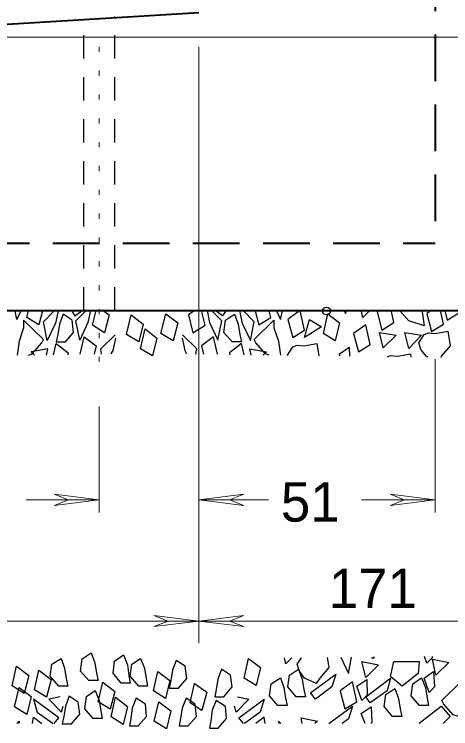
# Model space of a CAD drawing. Extents: x 312583 to 312854, y 144419 to 144597.
# Drawn here: x 312715.73 to 312724.13, y 144443.55 to 144457.33 of the extents above; entities that cross this region are included whole.
import ezdxf

# ---------------------------------------------------------------- set-up
doc = ezdxf.new("R2010")
doc.units = 0
doc.header["$LTSCALE"] = 0.3
doc.header["$PDMODE"] = 32
doc.header["$PDSIZE"] = 0.15
for name, pattern in [('DOTTED', [1.5, 0.3, -1.2]), ('MEDIUM_DASHED', [4.5, 3, -1.5]), ('SHORT_DASHED', [2.7, 1.5, -1.2])]:
    doc.linetypes.add(name, pattern=pattern)
doc.layers.add('1', color=7, linetype='Continuous', lineweight=25)
doc.layers.add('2', color=7, linetype='Continuous', lineweight=13)

msp = doc.modelspace()

# ---------------------------------------------------------------- linework, layer by layer
at = {"layer": '1', "linetype": 'MEDIUM_DASHED', "lineweight": 40}
for p in [(312723.8344, 144494.7404), (312698.9177, 144452.9187)]:
    msp.add_line(p, (312723.8344, 144452.9187), dxfattribs=at)
at = {"layer": '1', "lineweight": 40}
for p, q in [((312711.376, 144456.89), (312719.2804, 144457.3654)), ((312697.001, 144451.6154), (312725.751, 144451.6154))]:
    msp.add_line(p, q, dxfattribs=at)
at = {"layer": '1', "linetype": 'SHORT_DASHED'}
for p, q in [((312717.0647, 144451.6154), (312717.0647, 144457.258)), ((312717.6627, 144451.6154), (312717.6627, 144457.2964))]:
    msp.add_line(p, q, dxfattribs=at)
at = {"layer": '1'}
for p, q in [((312715.9684, 144451.485), (312715.999, 144451.6077)), ((312716.2904, 144451.4007), (312716.4974, 144451.6077)), ((312716.9114, 144451.416), (312717.1107, 144451.6154)), ((312717.2334, 144451.3317), (312717.3024, 144451.6154)), ((312719.403, 144451.3317), (312719.334, 144451.6154)), ((312719.725, 144451.416), (312719.5257, 144451.6154)), ((312720.346, 144451.4007), (312720.139, 144451.6077)), ((312720.668, 144451.485), (312720.6374, 144451.6077)), ((312721.3197, 144451.2397), (312721.2354, 144451.6077)), ((312723.037, 144451.3854), (312722.991, 144451.6)), ((312723.9954, 144451.3547), (312723.9417, 144451.5924)), ((312717.3944, 144450.8794), (312717.6704, 144451.1477)), ((312719.242, 144450.8794), (312718.966, 144451.1477)), ((312717.4097, 144450.772), (312717.3944, 144450.8794)), ((312719.2267, 144450.772), (312719.242, 144450.8794)), ((312722.1784, 144450.91), (312722.186, 144450.7337)), ((312716.0527, 144450.818), (312716.114, 144450.7567)), ((312720.5837, 144450.818), (312720.5224, 144450.7567)), ((312723.9494, 144450.7337), (312723.9417, 144450.7107)), ((312716.6124, 144444.1634), (312716.39, 144444.1174)), ((312720.024, 144444.1634), (312720.2464, 144444.1174)), ((312716.1677, 144443.872), (312716.4744, 144443.6497)), ((312720.461, 144443.872), (312720.162, 144443.6497)), ((312721.565, 144443.6957), (312721.519, 144443.6497)), ((312722.163, 144443.7417), (312722.0404, 144443.6497))]:
    msp.add_line(p, q, dxfattribs=at)
for points in [[(312715.8534, 144451.6077), (312715.7767, 144451.4467), (312715.746, 144451.6077)], [(312716.2674, 144451.6077), (312716.1984, 144451.3394), (312715.9684, 144451.485)], [(312716.574, 144451.6077), (312716.5204, 144451.37), (312716.3594, 144451.0404), (312716.2904, 144451.4007)], [(312716.827, 144451.6154), (312716.896, 144451.5157), (312717.0034, 144451.5924), (312717.0264, 144451.6154)], [(312717.195, 144451.6154), (312717.1414, 144451.3854), (312716.988, 144451.048), (312716.9114, 144451.416)], [(312717.4404, 144451.6154), (312717.5554, 144451.531), (312717.4634, 144451.186), (312717.2334, 144451.3317)], [(312719.196, 144451.6154), (312719.081, 144451.531), (312719.1654, 144451.186), (312719.403, 144451.3317)], [(312719.4414, 144451.6154), (312719.4874, 144451.3854), (312719.6484, 144451.048), (312719.725, 144451.416)], [(312719.8094, 144451.6154), (312719.7404, 144451.5157), (312719.633, 144451.5924), (312719.6024, 144451.6154)], [(312720.0624, 144451.6077), (312720.116, 144451.37), (312720.277, 144451.0404), (312720.346, 144451.4007)], [(312720.369, 144451.6077), (312720.438, 144451.3394), (312720.668, 144451.485)], [(312720.7754, 144451.6077), (312720.852, 144451.4467), (312720.8904, 144451.6077)], [(312721.22, 144451.6077), (312720.9977, 144451.4467), (312721.0897, 144451.094), (312721.3197, 144451.2397)], [(312722.0864, 144451.6), (312722.1094, 144451.5617), (312722.117, 144451.6)], [(312722.554, 144451.6), (312722.439, 144451.485), (312722.416, 144451.6)], [(312722.7304, 144451.6), (312722.715, 144451.5924), (312722.807, 144451.2397), (312723.037, 144451.3854)], [(312723.5814, 144451.5924), (312723.6197, 144451.324), (312723.3284, 144451.416), (312723.1674, 144451.6)], [(312723.727, 144451.5924), (312723.6734, 144451.5617), (312723.7654, 144451.209), (312723.9954, 144451.3547)], [(312724.026, 144451.5924), (312724.0644, 144451.4314), (312724.302, 144451.577)], [(312715.999, 144450.7567), (312716.068, 144450.7797), (312716.2597, 144450.9944), (312716.2904, 144451.0557), (312715.907, 144451.4314), (312715.907, 144451.2857)], [(312720.6374, 144450.7567), (312720.5684, 144450.7797), (312720.3767, 144450.9944), (312720.346, 144451.0557), (312720.7294, 144451.4314), (312720.7294, 144451.2857)], [(312715.907, 144451.2857), (312715.8227, 144451.025), (312715.7844, 144450.7567)], [(312720.7294, 144451.2857), (312720.8137, 144451.025), (312720.852, 144450.7567)], [(312723.6964, 144450.7184), (312723.658, 144450.7337), (312723.5584, 144450.864), (312723.52, 144450.9944), (312723.6197, 144451.1554), (312723.704, 144451.186), (312723.8344, 144451.1707), (312724.0797, 144451.2167), (312724.1257, 144450.933), (312723.9494, 144450.7337)], [(312716.9957, 144450.772), (312717.0724, 144451.1094), (312717.3024, 144450.933), (312717.264, 144450.772)], [(312717.678, 144451.0864), (312717.6244, 144450.8487), (312717.586, 144450.7797)], [(312718.9584, 144451.0864), (312719.012, 144450.8487), (312719.0427, 144450.7797)], [(312719.6407, 144450.772), (312719.564, 144451.1094), (312719.334, 144450.933), (312719.3724, 144450.772)], [(312716.344, 144450.7567), (312716.3747, 144450.8794), (312716.0527, 144450.818)], [(312716.482, 144450.7644), (312716.5357, 144450.979), (312716.7657, 144450.8027), (312716.758, 144450.7644)], [(312720.1544, 144450.7644), (312720.1007, 144450.979), (312719.8707, 144450.8027), (312719.8784, 144450.7644)], [(312720.2924, 144450.7567), (312720.2617, 144450.8794), (312720.5837, 144450.818)], [(312720.99, 144450.749), (312720.99, 144450.7567), (312721.0897, 144450.9177), (312721.174, 144450.9484), (312721.3044, 144450.933), (312721.5574, 144450.979), (312721.5957, 144450.7414)], [(312722.002, 144450.7337), (312721.9867, 144450.772), (312722.1784, 144450.91)], [(312722.9144, 144450.726), (312722.9757, 144450.749), (312723.106, 144450.7337), (312723.359, 144450.7797), (312723.3667, 144450.7184)], [(312721.7567, 144444.9224), (312721.7874, 144444.7307), (312721.611, 144444.5237)], [(312722.0174, 144444.93), (312722.163, 144444.6157), (312722.2244, 144444.93)], [(312722.6614, 144444.9377), (312722.6307, 144444.907), (312722.6154, 144444.93)], [(312723.773, 144444.9454), (312723.7807, 144444.9224), (312723.6734, 144444.815), (312723.6274, 144444.9454)], [(312721.0744, 144444.9147), (312720.9594, 144444.7997), (312720.9287, 144444.9147)], [(312721.611, 144444.5237), (312721.542, 144444.424), (312721.3197, 144444.5237), (312721.22, 144444.6617), (312721.174, 144444.792), (312721.2584, 144444.9147)], [(312716.4974, 144443.6497), (312716.5817, 144443.757), (312716.0987, 144444.1174), (312716.1677, 144443.872)], [(312716.39, 144444.1174), (312716.6354, 144443.872), (312716.666, 144443.987)], [(312720.2464, 144444.1174), (312720.001, 144443.872), (312719.9704, 144443.987)], [(312720.139, 144443.6497), (312720.0547, 144443.757), (312720.5377, 144444.1174), (312720.461, 144443.872)], [(312721.7874, 144443.6497), (312722.2397, 144443.987), (312722.163, 144443.7417)], [(312722.485, 144443.6497), (312722.4084, 144443.8414), (312722.6, 144443.9717)], [(312722.6, 144443.9717), (312722.6154, 144443.6727), (312722.5924, 144443.6497)], [(312723.5354, 144443.6497), (312723.5277, 144443.6574), (312723.9494, 144443.987)], [(312723.9494, 144443.987), (312724.1257, 144443.7877), (312723.9877, 144443.6497)], [(312715.7767, 144443.6497), (312715.8227, 144443.6957), (312715.815, 144443.6497)], [(312716.0757, 144443.6497), (312716.0987, 144443.7724), (312716.2597, 144443.6497)], [(312720.5607, 144443.6497), (312720.5377, 144443.7724), (312720.3767, 144443.6497)], [(312720.8597, 144443.6497), (312720.8137, 144443.6957), (312720.8214, 144443.6497)], [(312721.2737, 144443.6497), (312721.2507, 144443.757), (312721.565, 144443.6957)]]:
    msp.add_lwpolyline(points, dxfattribs=at)
for points in [[(312716.666, 144451.5464), (312716.597, 144451.3547), (312716.5664, 144451.1554), (312716.5357, 144451.0097), (312716.712, 144451.0097), (312716.8654, 144451.1937), (312716.8424, 144451.4314)], [(312718.552, 144451.1707), (312718.644, 144451.554), (312718.874, 144451.3777), (312718.7897, 144451.0327)], [(312719.9704, 144451.5464), (312720.0394, 144451.3547), (312720.07, 144451.1554), (312720.1007, 144451.0097), (312719.9244, 144451.0097), (312719.7634, 144451.1937), (312719.794, 144451.4314)], [(312721.68, 144451.1707), (312721.7644, 144451.554), (312721.9944, 144451.3777), (312721.91, 144451.0327)], [(312717.885, 144451.1554), (312717.977, 144451.531), (312718.207, 144451.3547), (312718.1227, 144451.0097)], [(312721.6417, 144451.301), (312721.3197, 144451.094), (312721.4117, 144451.4467)], [(312718.161, 144450.8794), (312718.2454, 144451.2627), (312718.4754, 144451.0864), (312718.391, 144450.7414)], [(312722.5847, 144450.9637), (312722.5004, 144451.3394), (312722.2627, 144451.1707), (312722.3547, 144450.818)], [(312723.083, 144451.14), (312722.83, 144450.8947), (312722.761, 144451.1937)], [(312723.5737, 144451.14), (312723.3284, 144450.887), (312723.2517, 144451.1937)], [(312717.2104, 144445.0144), (312717.2794, 144444.8227), (312717.31, 144444.6234), (312717.3407, 144444.4777), (312717.1644, 144444.4777), (312717.0034, 144444.6617), (312717.034, 144444.8994)], [(312717.8314, 144444.976), (312717.908, 144444.7844), (312717.931, 144444.5774), (312717.9617, 144444.4317), (312717.7854, 144444.4317), (312717.632, 144444.6234), (312717.655, 144444.8534)], [(312716.6277, 144444.907), (312716.6967, 144444.7154), (312716.7274, 144444.516), (312716.758, 144444.3704), (312716.5817, 144444.3704), (312716.4207, 144444.562), (312716.4514, 144444.792)], [(312718.161, 144444.907), (312718.2377, 144444.7154), (312718.2684, 144444.516), (312718.2914, 144444.3704), (312718.1227, 144444.3704), (312717.9617, 144444.562), (312717.9924, 144444.792)], [(312718.8434, 144444.8687), (312718.7744, 144444.677), (312718.7437, 144444.4777), (312718.713, 144444.332), (312718.8894, 144444.332), (312719.0504, 144444.516), (312719.0197, 144444.7537)], [(312720.1544, 144444.5237), (312720.2387, 144444.907), (312720.4687, 144444.7307), (312720.3844, 144444.3857)], [(312722.7457, 144444.7844), (312722.5004, 144444.539), (312722.4237, 144444.8457)], [(312723.5047, 144444.6157), (312723.198, 144444.3704), (312722.9757, 144444.5544), (312723.037, 144444.8457), (312723.5277, 144444.8457)], [(312724.095, 144444.8304), (312723.8497, 144444.585), (312723.7807, 144444.8917)], [(312715.6847, 144444.378), (312715.769, 144444.7537), (312716.0067, 144444.5774), (312715.9147, 144444.2324)], [(312716.114, 144444.3014), (312716.1984, 144444.677), (312716.436, 144444.5007), (312716.344, 144444.1557)], [(312718.4064, 144444.2784), (312718.4907, 144444.654), (312718.7207, 144444.4777), (312718.6364, 144444.1327)], [(312719.7174, 144444.7), (312719.6484, 144444.5084), (312719.6177, 144444.309), (312719.587, 144444.1634), (312719.7634, 144444.1634), (312719.9244, 144444.355), (312719.8937, 144444.585)], [(312721.2047, 144444.7), (312721.2737, 144444.5084), (312721.3044, 144444.309), (312721.335, 144444.1634), (312721.1587, 144444.1634), (312720.9977, 144444.355), (312721.0284, 144444.585)], [(312723.8037, 144444.654), (312723.819, 144444.355), (312723.7194, 144444.2477), (312723.6197, 144444.5237)], [(312720.852, 144444.5314), (312720.921, 144444.3474), (312720.9517, 144444.1404), (312720.9824, 144443.9947), (312720.806, 144443.9947), (312720.645, 144444.1864), (312720.6757, 144444.4164)], [(312721.841, 144444.355), (312721.5267, 144444.1174), (312721.4347, 144444.24), (312721.9177, 144444.6004)], [(312722.9067, 144444.2784), (312722.5847, 144444.0484), (312722.5004, 144444.1634), (312722.9757, 144444.5237)], [(312723.5737, 144444.5314), (312723.6504, 144444.3474), (312723.681, 144444.1404), (312723.704, 144443.9947), (312723.5354, 144443.9947), (312723.3744, 144444.1864), (312723.405, 144444.4164)], [(312717.3407, 144444.0714), (312717.4327, 144444.447), (312717.6627, 144444.2707), (312717.5707, 144443.9257)], [(312719.1117, 144444.0484), (312719.196, 144444.424), (312719.4337, 144444.2554), (312719.3417, 144443.9027)], [(312722.324, 144444.0714), (312722.2397, 144444.4547), (312722.002, 144444.2784), (312722.094, 144443.9334)], [(312722.5157, 144444.5007), (312722.5234, 144444.194), (312722.4237, 144444.0944), (312722.324, 144444.3704)], [(312724.3404, 144444.3244), (312724.4324, 144444.0637), (312724.4707, 144443.7264), (312724.1794, 144443.8184), (312723.9954, 144444.033), (312723.9647, 144444.0944), (312724.3404, 144444.47)], [(312715.7307, 144443.9717), (312715.8227, 144444.3474), (312716.0527, 144444.171), (312715.9684, 144443.826)], [(312717.287, 144444.286), (312717.3637, 144444.0944), (312717.3944, 144443.895), (312717.4174, 144443.7494), (312717.2487, 144443.7494), (312717.0877, 144443.9334), (312717.1184, 144444.171)], [(312723.06, 144444.3244), (312723.129, 144444.1327), (312723.1597, 144443.9334), (312723.1904, 144443.7877), (312723.014, 144443.7877), (312722.853, 144443.9794), (312722.8837, 144444.2094)], [(312716.781, 144444.1787), (312716.712, 144443.987), (312716.6814, 144443.7877), (312716.6507, 144443.642), (312716.827, 144443.642), (312716.988, 144443.8337), (312716.9574, 144444.0637)], [(312717.5937, 144443.78), (312717.678, 144444.1557), (312717.908, 144443.9794), (312717.8237, 144443.6344)], [(312718.0767, 144444.1404), (312718, 144443.9487), (312717.9694, 144443.7494), (312717.9464, 144443.6037), (312718.115, 144443.6037), (312718.276, 144443.7877), (312718.253, 144444.0254)], [(312719.035, 144444.1404), (312718.9584, 144443.9487), (312718.9277, 144443.7494), (312718.9047, 144443.6037), (312719.0734, 144443.6037), (312719.2344, 144443.7877), (312719.2114, 144444.0254)], [(312719.6177, 144444.0944), (312719.541, 144443.9104), (312719.5104, 144443.7034), (312719.4874, 144443.5577), (312719.656, 144443.5577), (312719.817, 144443.7494), (312719.794, 144443.9794)], [(312718.4217, 144443.6957), (312718.5137, 144444.0714), (312718.7437, 144443.895), (312718.6594, 144443.55)]]:
    msp.add_lwpolyline(points, close=True, dxfattribs=at)
msp.add_point((312721.7414, 144451.6077), dxfattribs=at)
at = {"layer": '2'}
for p, q in [((312713.1087, 144456.89), (312728.9864, 144456.89)), ((312719.2804, 144456.706), (312719.2804, 144445.1984)), ((312723.8344, 144450.68), (312723.8344, 144447.7207)), ((312717.3637, 144449.7677), (312717.3637, 144447.7207)), ((312715.953, 144447.966), (312717.3637, 144447.966)), ((312716.4974, 144448.0734), (312716.7734, 144447.966)), ((312717.3637, 144447.966), (312716.4974, 144448.0734)), ((312716.4974, 144447.8587), (312716.7734, 144447.966)), ((312717.3637, 144447.966), (312716.4974, 144447.8587)), ((312719.2804, 144447.966), (312720.1467, 144448.0734)), ((312719.2804, 144447.966), (312720.622, 144447.966)), ((312719.2804, 144447.966), (312720.1467, 144447.8587)), ((312720.1467, 144448.0734), (312719.8707, 144447.966)), ((312720.1467, 144447.8587), (312719.8707, 144447.966)), ((312722.416, 144447.966), (312723.8344, 144447.966)), ((312722.968, 144448.0734), (312723.244, 144447.966)), ((312723.8344, 144447.966), (312722.968, 144448.0734)), ((312722.968, 144447.8587), (312723.244, 144447.966)), ((312723.8344, 144447.966), (312722.968, 144447.8587)), ((312703.464, 144445.6277), (312719.2804, 144445.6277)), ((312718.414, 144445.735), (312718.69, 144445.6277)), ((312719.2804, 144445.6277), (312718.414, 144445.735)), ((312718.414, 144445.5204), (312718.69, 144445.6277)), ((312719.2804, 144445.6277), (312718.414, 144445.5204)), ((312719.2804, 144445.6277), (312720.1467, 144445.735)), ((312719.2804, 144445.6277), (312725.751, 144445.6277)), ((312719.2804, 144445.6277), (312720.1467, 144445.5204)), ((312720.1467, 144445.735), (312719.8707, 144445.6277)), ((312720.1467, 144445.5204), (312719.8707, 144445.6277))]:
    msp.add_line(p, q, dxfattribs=at)
at = {"layer": '2', "linetype": 'DOTTED'}
msp.add_line((312717.3637, 144456.706), (312717.3637, 144450.565), dxfattribs=at)

# ---------------------------------------------------------------- texts
at = {"layer": '2'}
for s, p in [('51 ', (312720.8626, 144447.5448)), ('171 ', (312721.785, 144445.8774))]:
    msp.add_text(s, height=0.76, dxfattribs=at).set_placement(p)

doc.saveas('drawing.dxf')
